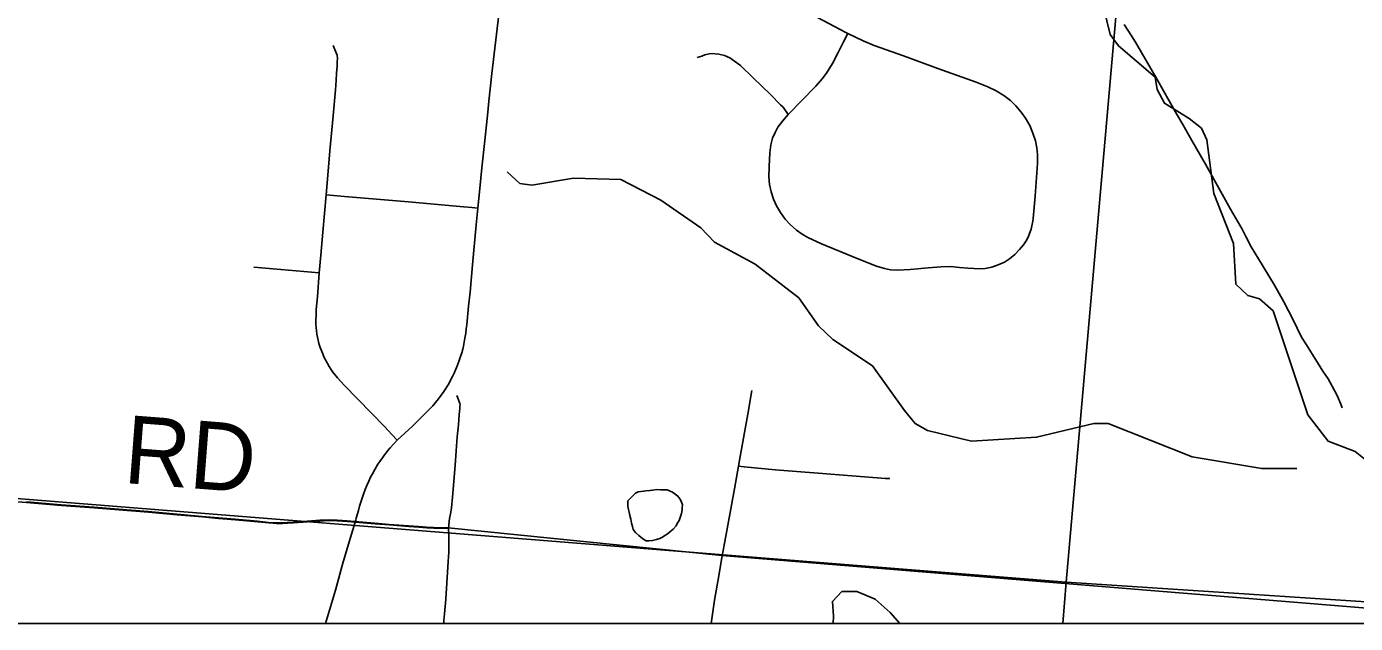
# Model space of a CAD drawing. Extents: x 0 to 34, y 0 to 22.
# Drawn here: x 5.745 to 6.856, y 14.306 to 14.804 of the extents above; entities that cross this region are included whole.
import ezdxf

# ---------------------------------------------------------------- set-up
doc = ezdxf.new("R2010")
doc.units = 0
for name, color, linetype in [('GM_X_Corporation', 7, 'Continuous'), ('GM_X_County_Road', 7, 'Continuous'), ('GM_X_County_Road_Text', 7, 'Continuous'), ('GM_X_Minor_Lake', 7, 'Continuous'), ('GM_X_Minor_River', 7, 'Continuous'), ('GM_X_Township_Road', 7, 'Continuous')]:
    doc.layers.add(name, color=color, linetype=linetype)

msp = doc.modelspace()

# ---------------------------------------------------------------- linework, layer by layer
at = {"layer": 'GM_X_Corporation'}
for points in [[(3.4381, 14.3059), (8.7119, 14.3059), (8.7119, 21.1059)], [(3.4381, 14.3059), (7.0231, 14.3059), (6.3265, 14.3627), (6.0974, 14.3857), (6.0852, 14.386), (6.0794, 14.3863), (6.0727, 14.3867), (6.0644, 14.3873), (6.048, 14.3886), (6.0362, 14.3896), (6.0194, 14.391), (6.0131, 14.3915), (6.0045, 14.3921), (5.9984, 14.3923), (5.9958, 14.3922), (5.9934, 14.3921), (5.99, 14.392), (5.9797, 14.3913), (5.968, 14.3905), (5.9629, 14.3901), (5.9588, 14.3899), (5.956, 14.3898), (5.9537, 14.3898), (5.951, 14.39), (5.9472, 14.3903), (5.9381, 14.3912), (5.9192, 14.3929), (5.9053, 14.3942), (5.8917, 14.3953), (5.8705, 14.3972), (5.8466, 14.3993), (5.8217, 14.4013), (5.801, 14.4029), (5.7738, 14.405), (5.7447, 14.4073)], [(5.7447, 14.4073), (5.7738, 14.405), (5.801, 14.4029), (5.8217, 14.4013), (5.8466, 14.3993), (5.8705, 14.3972), (5.8917, 14.3953), (5.9053, 14.3942), (5.9192, 14.3929), (5.9381, 14.3912), (5.9472, 14.3903), (5.951, 14.39), (5.9537, 14.3898), (5.956, 14.3898), (5.9588, 14.3899), (5.9629, 14.3901), (5.968, 14.3905), (5.9797, 14.3913), (5.99, 14.392), (5.9934, 14.3921), (5.9958, 14.3922), (5.9984, 14.3923), (6.0045, 14.3921), (6.0131, 14.3915), (6.0194, 14.391), (6.0362, 14.3896), (6.048, 14.3886), (6.0644, 14.3873), (6.0727, 14.3867), (6.0794, 14.3863), (6.0852, 14.386), (6.0974, 14.3857), (6.3265, 14.3627), (7.0231, 14.3059)]]:
    msp.add_lwpolyline(points, dxfattribs=at)
for points in [[(6.7026, 15.345), (6.6144, 14.3404), (5.5964, 14.4213), (5.6726, 15.4318)], [(7.6585, 15.2849), (7.6759, 15.2839), (6.9714, 14.3168), (6.6144, 14.3404), (6.7026, 15.345)], [(5.5877, 14.3059), (6.6115, 14.3059), (6.6144, 14.3404), (5.5964, 14.4213)], [(6.6115, 14.3059), (6.9682, 14.3059), (6.9714, 14.3168), (6.6144, 14.3404)]]:
    msp.add_lwpolyline(points, close=True, dxfattribs=at)
at = {"layer": 'GM_X_County_Road'}
for points in [[(6.1223, 14.6527), (6.1239, 14.6692), (6.1256, 14.6864), (6.128, 14.7092), (6.1306, 14.733), (6.1315, 14.7421), (6.134, 14.7653), (6.1397, 14.8147), (6.1436, 14.8479), (6.1455, 14.8634), (6.1483, 14.884)], [(6.0549, 14.4589), (6.0675, 14.4707), (6.0785, 14.4814), (6.0811, 14.484), (6.0845, 14.4877), (6.087, 14.4905), (6.0895, 14.4936), (6.0939, 14.4997), (6.0979, 14.5061), (6.0995, 14.509), (6.1011, 14.5122), (6.1025, 14.515), (6.104, 14.5184), (6.1053, 14.5217), (6.1067, 14.5255), (6.1079, 14.5288), (6.1088, 14.532), (6.1096, 14.5349), (6.1102, 14.5375), (6.1109, 14.5409), (6.1115, 14.5443), (6.1121, 14.5483), (6.1126, 14.552), (6.113, 14.5554), (6.1146, 14.5709), (6.1158, 14.5826), (6.1179, 14.6055), (6.121, 14.6389), (6.1223, 14.6527)], [(6.0197, 14.3905), (6.0201, 14.3921), (6.0206, 14.3937), (6.0224, 14.4001), (6.0234, 14.4037), (6.0267, 14.4138), (6.0281, 14.4177), (6.0295, 14.4212), (6.031, 14.4247), (6.0326, 14.428), (6.0341, 14.4309), (6.0361, 14.4344), (6.0387, 14.4388), (6.0403, 14.4412), (6.0424, 14.4443), (6.0442, 14.4466), (6.0456, 14.4485), (6.0471, 14.4504), (6.0489, 14.4525), (6.0518, 14.4557), (6.0549, 14.4589)], [(5.7195, 14.4088), (5.7449, 14.4068), (5.774, 14.4045), (5.8013, 14.4024), (5.822, 14.4008), (5.8469, 14.3987), (5.8707, 14.3967), (5.8919, 14.3948), (5.9055, 14.3936), (5.9195, 14.3924), (5.9383, 14.3907), (5.9474, 14.3898), (5.9512, 14.3895), (5.9539, 14.3893), (5.9562, 14.3893), (5.959, 14.3894), (5.9631, 14.3896), (5.9682, 14.3899), (5.98, 14.3908), (5.9902, 14.3914), (5.9936, 14.3916), (5.996, 14.3917), (5.9986, 14.3918), (6.0047, 14.3916), (6.0133, 14.391), (6.0197, 14.3905)], [(5.995, 14.3059), (6.0031, 14.3337), (6.0093, 14.3563), (6.0139, 14.3712), (6.0197, 14.3905)], [(6.0197, 14.3905), (6.0364, 14.389), (6.0483, 14.3881), (6.0646, 14.3868), (6.0729, 14.3862), (6.0797, 14.3858), (6.0854, 14.3855), (6.0976, 14.3852)]]:
    msp.add_lwpolyline(points, dxfattribs=at)
at = {"layer": 'GM_X_Minor_Lake'}
msp.add_line((6.4198, 14.312), (6.4194, 14.3059), dxfattribs=at)
for points in [[(6.2478, 14.4083), (6.254, 14.4146), (6.2563, 14.4157), (6.2586, 14.416), (6.2609, 14.4163), (6.2628, 14.4167), (6.2662, 14.4169), (6.2685, 14.4173), (6.2716, 14.4176), (6.275, 14.4175), (6.2784, 14.4174), (6.2807, 14.4174), (6.2825, 14.4166), (6.2852, 14.4154), (6.2874, 14.4138), (6.2896, 14.4122), (6.2911, 14.4099), (6.2922, 14.408), (6.2933, 14.4049), (6.2932, 14.4026), (6.2932, 14.4007), (6.2927, 14.3977), (6.2915, 14.3943), (6.2907, 14.3917), (6.2891, 14.3894), (6.288, 14.3875), (6.2856, 14.3846), (6.2806, 14.3805), (6.2787, 14.3794), (6.2767, 14.3779), (6.2744, 14.3768), (6.2718, 14.3761), (6.2683, 14.3751), (6.2653, 14.3748), (6.263, 14.3748), (6.2604, 14.3764), (6.257, 14.3792), (6.2541, 14.3819), (6.2522, 14.3842), (6.2515, 14.3869), (6.2508, 14.3896), (6.2501, 14.393), (6.2494, 14.3961), (6.2487, 14.3987), (6.2484, 14.401), (6.2477, 14.4037), (6.2478, 14.406), (6.2478, 14.4068), (6.2478, 14.4071), (6.2478, 14.4083)], [(6.4753, 14.3059), (6.4672, 14.3151), (6.4545, 14.326), (6.4391, 14.3325), (6.4266, 14.3324), (6.4188, 14.3242), (6.4198, 14.312)]]:
    msp.add_lwpolyline(points, dxfattribs=at)
at = {"layer": 'GM_X_Minor_River'}
for points in [[(6.8657, 14.4417), (6.856, 14.4495), (6.8334, 14.458), (6.8163, 14.48), (6.7873, 14.5669), (6.7761, 14.5771), (6.7663, 14.5799), (6.7562, 14.5893), (6.7542, 14.6232), (6.7379, 14.6649), (6.732, 14.7099), (6.7276, 14.7195), (6.7171, 14.7277), (6.6965, 14.7404), (6.6903, 14.7519), (6.6886, 14.7622), (6.658, 14.7883), (6.651, 14.798), (6.6429, 14.8312)], [(6.8071, 14.4354), (6.7779, 14.4352), (6.7197, 14.4449), (6.6493, 14.473), (6.6375, 14.4729), (6.5895, 14.4614), (6.5352, 14.4581), (6.4982, 14.4669), (6.4881, 14.4728), (6.4792, 14.4836), (6.4522, 14.5211), (6.4192, 14.5431), (6.4073, 14.5544), (6.3907, 14.5779), (6.3541, 14.6061), (6.3203, 14.6243), (6.3087, 14.6363), (6.2754, 14.6595), (6.242, 14.6766), (6.2022, 14.6778), (6.1675, 14.6721), (6.1573, 14.6735), (6.1469, 14.6832)]]:
    msp.add_lwpolyline(points, dxfattribs=at)
at = {"layer": 'GM_X_Township_Road'}
msp.add_line((6.3241, 14.3475), (6.3267, 14.3622), dxfattribs=at)
for points in [[(6.3706, 14.8702), (6.3713, 14.866), (6.3725, 14.8606), (6.3736, 14.8556), (6.3789, 14.8404), (6.3821, 14.833), (6.3844, 14.8288), (6.3874, 14.8249), (6.3913, 14.8211), (6.3951, 14.8182), (6.4015, 14.8145), (6.4301, 14.7996), (6.4317, 14.7988)], [(6.7689, 14.6206), (6.7645, 14.6292), (6.7614, 14.6352), (6.7518, 14.6519), (6.7309, 14.6895), (6.7195, 14.7092), (6.7118, 14.7227), (6.7066, 14.7317), (6.6958, 14.7509), (6.6903, 14.7603), (6.6722, 14.7915), (6.669, 14.7968), (6.6627, 14.8062)], [(6.3818, 14.731), (6.4049, 14.7548), (6.4102, 14.7608), (6.4139, 14.7657), (6.4188, 14.7736), (6.4237, 14.7828), (6.4282, 14.7917), (6.4317, 14.7988)], [(6.4317, 14.7988), (6.4446, 14.7925), (6.4538, 14.7888), (6.4783, 14.78), (6.5069, 14.7696), (6.539, 14.758), (6.5489, 14.7542), (6.5557, 14.7508), (6.5621, 14.7469), (6.5677, 14.7427), (6.5723, 14.7384), (6.5768, 14.7331), (6.5804, 14.7279), (6.5838, 14.7219), (6.5865, 14.7155), (6.5886, 14.7089), (6.5898, 14.7033), (6.5903, 14.6977), (6.5902, 14.6901), (6.5883, 14.6628), (6.5867, 14.6442), (6.5863, 14.6418)], [(5.9954, 14.6638), (5.9968, 14.6803), (5.9986, 14.7008), (6.0012, 14.7299), (6.0031, 14.7516), (6.0037, 14.7594), (6.0041, 14.7656), (6.0045, 14.7714), (6.0047, 14.7755), (6.0048, 14.7774), (6.0048, 14.7787), (6.0047, 14.7797), (6.0046, 14.7804), (6.0045, 14.781), (6.0042, 14.7818), (6.0039, 14.7826), (6.0012, 14.7888)], [(6.3057, 14.7786), (6.3096, 14.7799), (6.3121, 14.7809), (6.3158, 14.7817), (6.3183, 14.7819), (6.3207, 14.7818), (6.3238, 14.7814), (6.3285, 14.7802), (6.3329, 14.7783), (6.337, 14.7757), (6.3419, 14.772), (6.3528, 14.7614), (6.3669, 14.7477), (6.3755, 14.7392), (6.3775, 14.7372), (6.3818, 14.731)], [(6.5098, 14.6039), (6.499, 14.6029), (6.4838, 14.6015), (6.4731, 14.601), (6.4674, 14.6013), (6.4624, 14.6023), (6.4558, 14.6043), (6.4395, 14.6106), (6.4097, 14.6229), (6.3983, 14.6282), (6.3934, 14.631), (6.3888, 14.6343), (6.3836, 14.639), (6.3794, 14.6436), (6.3753, 14.6492), (6.3721, 14.6547), (6.3695, 14.6604), (6.3675, 14.6664), (6.3663, 14.6726), (6.3657, 14.6789), (6.3658, 14.6877), (6.3664, 14.6989), (6.3674, 14.7058), (6.3688, 14.7113), (6.3708, 14.716), (6.3733, 14.7204), (6.377, 14.7256), (6.3818, 14.731)], [(5.9897, 14.5987), (5.991, 14.6136), (5.9927, 14.6326), (5.9954, 14.6638)], [(5.9954, 14.6638), (6.0108, 14.6625), (6.0642, 14.658), (6.0828, 14.6563), (6.0979, 14.655), (6.1102, 14.6538), (6.1172, 14.6532), (6.1223, 14.6527)], [(6.5863, 14.6418), (6.5856, 14.6379), (6.5849, 14.6351), (6.5837, 14.6315), (6.5827, 14.6291), (6.5809, 14.6255), (6.5785, 14.6222), (6.5753, 14.6183), (6.5713, 14.6142), (6.567, 14.6105), (6.5627, 14.6078), (6.5575, 14.6054), (6.5521, 14.6035), (6.5465, 14.6024), (6.542, 14.6021), (6.532, 14.6026), (6.5252, 14.6033), (6.5178, 14.604), (6.5098, 14.6039)], [(6.845, 14.486), (6.844, 14.4889), (6.841, 14.4962), (6.8369, 14.5041), (6.8333, 14.5102), (6.829, 14.5165), (6.8245, 14.5238), (6.8211, 14.529), (6.818, 14.5342), (6.8147, 14.5394), (6.8112, 14.5451), (6.8074, 14.5524), (6.8038, 14.56), (6.8003, 14.567), (6.7963, 14.5744), (6.7885, 14.5884), (6.7751, 14.6104), (6.7689, 14.6206)], [(5.9349, 14.6035), (5.951, 14.6021), (5.9897, 14.5987)], [(6.0549, 14.4589), (6.0503, 14.4638), (6.0445, 14.4702), (6.0104, 14.5048), (6.005, 14.5109), (6.0011, 14.5158), (5.9994, 14.5183), (5.998, 14.5206), (5.9948, 14.526), (5.9936, 14.5287), (5.9925, 14.5312), (5.9905, 14.5365), (5.9894, 14.5397), (5.9887, 14.5425), (5.9881, 14.5451), (5.9877, 14.5475), (5.9873, 14.5502), (5.987, 14.5531), (5.9869, 14.556), (5.9869, 14.5588), (5.987, 14.5636), (5.9872, 14.5682), (5.9881, 14.5788), (5.9897, 14.5987)], [(6.0976, 14.3852), (6.0982, 14.391), (6.0985, 14.3935), (6.0991, 14.3959), (6.0996, 14.3988), (6.1002, 14.4025), (6.1012, 14.4114), (6.1032, 14.4379), (6.1041, 14.4501), (6.1051, 14.4618), (6.106, 14.4719), (6.1067, 14.4803), (6.1071, 14.4854), (6.1073, 14.4874), (6.1074, 14.4885), (6.1072, 14.4897), (6.107, 14.4904), (6.1062, 14.4926), (6.1046, 14.4963)], [(6.3402, 14.4371), (6.3417, 14.4452), (6.3481, 14.4808), (6.3513, 14.5004)], [(6.3267, 14.3622), (6.3284, 14.3712), (6.3368, 14.4183), (6.3402, 14.4371)], [(6.3402, 14.4371), (6.345, 14.4367), (6.371, 14.4343), (6.4069, 14.4314), (6.4632, 14.427), (6.4669, 14.4268)], [(6.0939, 14.3059), (6.0939, 14.3082), (6.0944, 14.3138), (6.0947, 14.3169), (6.0954, 14.3262), (6.0975, 14.3575), (6.098, 14.3654), (6.0979, 14.3704), (6.098, 14.3756), (6.0979, 14.3799), (6.0976, 14.3852)], [(6.3175, 14.3059), (6.3177, 14.3077), (6.3201, 14.3253), (6.3237, 14.3455), (6.3241, 14.3475)]]:
    msp.add_lwpolyline(points, dxfattribs=at)

# ---------------------------------------------------------------- texts
at = {"layer": 'GM_X_County_Road_Text'}
msp.add_text('RD', height=0.05682, rotation=355.5697, dxfattribs=at).set_placement((5.8251, 14.4233))

doc.saveas('drawing.dxf')
